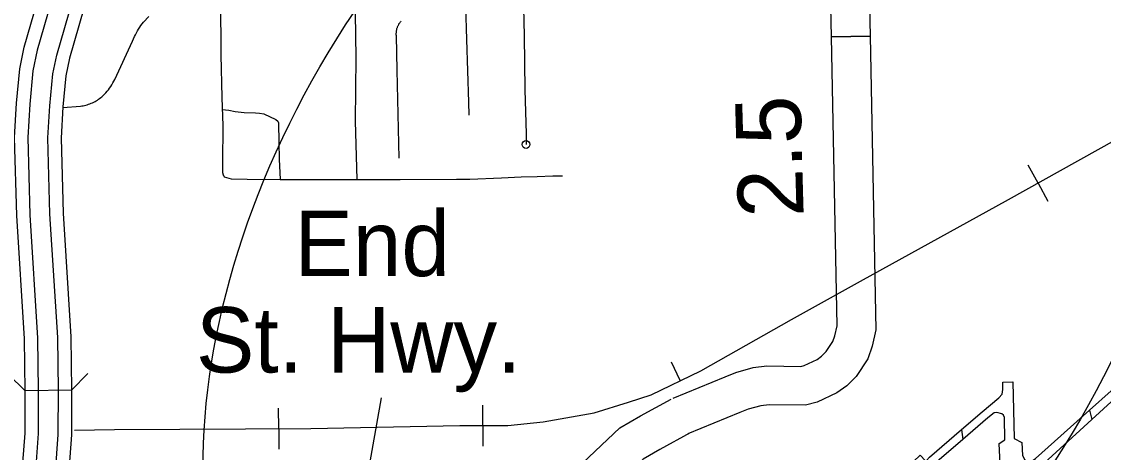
# Model space of a CAD drawing. Extents: x 309348 to 309445, y 336383 to 336484.
# Drawn here: x 309351.067 to 309352.465, y 336399.638 to 336400.194 of the extents above; entities that cross this region are included whole.
import ezdxf

# ---------------------------------------------------------------- set-up
doc = ezdxf.new("R2010")
doc.units = 0
doc.layers.add('R_Annotation', color=7, linetype='Continuous')

msp = doc.modelspace()

# ---------------------------------------------------------------- linework, layer by layer
at = {"layer": 'R_Annotation'}
for p, q in [((309352.1133, 336400.1741), (309352.1634, 336400.1751)), ((309352.3805, 336399.9852), (309352.3676, 336400.0083)), ((309352.3805, 336399.9852), (309352.3933, 336399.9621)), ((309351.918, 336399.7302), (309351.9065, 336399.754)), ((309351.1312, 336399.7179), (309351.0712, 336399.7171)), ((309351.1012, 336399.7175), (309351.1012, 336399.7175)), ((309351.5313, 336399.7081), (309351.4776, 336399.4011)), ((309351.399, 336399.6682), (309351.3988, 336399.6946)), ((309351.663, 336399.672), (309351.663, 336399.6984)), ((309351.399, 336399.6682), (309351.3991, 336399.6418)), ((309351.663, 336399.672), (309351.663, 336399.6456))]:
    msp.add_line(p, q, dxfattribs=at)
msp.add_lwpolyline([(309352.0852, 336401.5472), (309352.1342, 336401.5816), (309352.1376, 336401.4649), (309352.1413, 336401.2113), (309352.1414, 336401.1436), (309352.1437, 336401.068), (309352.1443, 336400.9364), (309352.1473, 336400.8071), (309352.1554, 336400.5429), (309352.1634, 336400.1751), (309352.1133, 336400.1741), (309352.1054, 336400.5416), (309352.0973, 336400.8057), (309352.0943, 336400.9357), (309352.0936, 336401.0671), (309352.0914, 336401.1428), (309352.0913, 336401.2109), (309352.0876, 336401.4638)], close=True, dxfattribs=at)
for points in [[(309351.0727, 336399.4543), (309351.0557, 336399.4536), (309351.0515, 336399.4801), (309351.0657, 336399.5912), (309351.071, 336399.6624), (309351.0712, 336399.7171), (309351.0703, 336399.7842), (309351.0603, 336399.9436), (309351.0576, 336400.0443), (309351.0601, 336400.0883), (309351.0645, 336400.1326), (309351.0701, 336400.1608), (309351.1591, 336400.4684), (309351.1742, 336400.5173), (309351.1893, 336400.5085)], [(309351.1893, 336400.5085), (309351.1754, 336400.4635), (309351.0867, 336400.1568), (309351.0813, 336400.1301), (309351.0771, 336400.087), (309351.0746, 336400.0441), (309351.0773, 336399.9444), (309351.0873, 336399.7849), (309351.0882, 336399.7173), (309351.088, 336399.6617), (309351.0827, 336399.5895), (309351.0684, 336399.4788), (309351.0727, 336399.4543)], [(309351.2142, 336400.5011), (309351.2313, 336400.4986), (309351.2166, 336400.4512), (309351.1285, 336400.1465), (309351.1239, 336400.1237), (309351.1199, 336400.0836), (309351.1177, 336400.0434), (309351.1203, 336399.9463), (309351.1303, 336399.7865), (309351.1312, 336399.7179), (309351.131, 336399.6601), (309351.1255, 336399.5852), (309351.114, 336399.4958), (309351.1114, 336399.4754), (309351.1057, 336399.4547), (309351.0887, 336399.4547)], [(309351.0887, 336399.4547), (309351.0944, 336399.4767), (309351.0971, 336399.4979), (309351.1086, 336399.5869), (309351.114, 336399.6607), (309351.1142, 336399.7177), (309351.1133, 336399.7858), (309351.1033, 336399.9456), (309351.1006, 336400.0437), (309351.103, 336400.085), (309351.1071, 336400.1262), (309351.112, 336400.1506), (309351.2003, 336400.4561), (309351.2142, 336400.5011)], [(309351.6156, 336400.2798), (309351.6185, 336400.2719), (309351.6226, 336400.2646), (309351.6252, 336400.2617), (309351.6287, 336400.2592), (309351.6338, 336400.2585), (309351.657, 336400.2601), (309351.6964, 336400.2624), (309351.7068, 336400.2611), (309351.7126, 336400.2576), (309351.7142, 336400.2544), (309351.7145, 336400.2487), (309351.7164, 336400.1756), (309351.7173, 336400.1057), (309351.7186, 336400.0488), (309351.7186, 336400.0351)], [(309351.6393, 336400.2572), (309351.6419, 336400.1707)], [(309351.4972, 336400.2338), (309351.4985, 336400.147), (309351.4982, 336400.1064)], [(309351.1349, 336399.6663), (309351.1866, 336399.6672), (309351.4404, 336399.6684), (309351.6331, 336399.672), (309351.6949, 336399.672), (309351.7409, 336399.6769), (309351.8069, 336399.6884), (309351.8512, 336399.7023), (309351.8802, 336399.712), (309351.9445, 336399.7429), (309352.062, 336399.809), (309352.151, 336399.8586), (309352.3425, 336399.9641), (309352.5254, 336400.0659), (309352.692, 336400.158), (309352.8047, 336400.2198)], [(309351.1349, 336399.6663), (309351.1866, 336399.6672), (309351.4404, 336399.6684), (309351.6331, 336399.672), (309351.6949, 336399.672), (309351.7409, 336399.6769), (309351.8069, 336399.6884), (309351.8512, 336399.7023), (309351.8802, 336399.712), (309351.9445, 336399.7429), (309352.062, 336399.809), (309352.151, 336399.8586), (309352.3425, 336399.9641), (309352.5254, 336400.0659), (309352.692, 336400.158), (309352.8047, 336400.2198)], [(309351.3237, 336400.2223), (309351.3243, 336400.151), (309351.3254, 336400.0959), (309351.3269, 336400.0591), (309351.3262, 336400.012), (309351.3263, 336399.9995), (309351.3263, 336399.9991), (309351.3264, 336399.9987), (309351.3264, 336399.9983), (309351.3265, 336399.998), (309351.3266, 336399.9976), (309351.3267, 336399.9973), (309351.3268, 336399.9969), (309351.3269, 336399.9965), (309351.327, 336399.9962), (309351.3271, 336399.9958), (309351.3273, 336399.9955), (309351.3274, 336399.9952), (309351.3276, 336399.9948), (309351.3278, 336399.9945), (309351.328, 336399.9942), (309351.3282, 336399.9939), (309351.3284, 336399.9936), (309351.3285, 336399.9935)], [(309351.1199, 336400.083), (309351.1427, 336400.0847), (309351.1445, 336400.0849), (309351.1463, 336400.0852), (309351.1481, 336400.0856), (309351.1498, 336400.086), (309351.1515, 336400.0865), (309351.1532, 336400.0871), (309351.1549, 336400.0877), (309351.1566, 336400.0884), (309351.1583, 336400.0891), (309351.1599, 336400.0899), (309351.1615, 336400.0907), (309351.163, 336400.0916), (309351.1646, 336400.0925), (309351.1661, 336400.0935), (309351.1675, 336400.0945), (309351.169, 336400.0956), (309351.1704, 336400.0968), (309351.1717, 336400.0979), (309351.173, 336400.0992), (309351.1743, 336400.1004), (309351.1755, 336400.1018), (309351.1772, 336400.1038), (309351.1789, 336400.1058), (309351.1804, 336400.1079), (309351.1819, 336400.1101), (309351.1833, 336400.1123), (309351.1846, 336400.1146), (309351.1858, 336400.1169), (309351.187, 336400.1192), (309351.2099, 336400.1686), (309351.2126, 336400.1744), (309351.2137, 336400.1769), (309351.215, 336400.1793), (309351.2163, 336400.1817), (309351.2178, 336400.1841), (309351.2193, 336400.1864), (309351.2208, 336400.1886), (309351.2225, 336400.1908), (309351.2242, 336400.1929), (309351.2309, 336400.2002)], [(309351.557, 336400.1942), (309351.5564, 336400.1936), (309351.5559, 336400.193), (309351.5554, 336400.1923), (309351.5549, 336400.1917), (309351.5544, 336400.191), (309351.554, 336400.1903), (309351.5536, 336400.1896), (309351.5532, 336400.1889), (309351.5528, 336400.1881), (309351.5525, 336400.1874), (309351.5522, 336400.1866), (309351.5519, 336400.1858), (309351.5516, 336400.1851), (309351.5514, 336400.1843), (309351.5512, 336400.1835), (309351.551, 336400.1827), (309351.5508, 336400.1819), (309351.5507, 336400.181), (309351.5506, 336400.1802), (309351.5506, 336400.1794), (309351.5505, 336400.1786), (309351.5505, 336400.1778), (309351.5505, 336400.1769), (309351.5506, 336400.1761), (309351.5506, 336400.1753), (309351.5516, 336400.1312), (309351.5543, 336400.0176)], [(309351.6419, 336400.1707), (309351.6442, 336400.0897)], [(309351.9089, 336399.7077), (309351.976, 336399.7352), (309351.9898, 336399.7408), (309352.0123, 336399.7469), (309352.0301, 336399.7491), (309352.074, 336399.7485), (309352.0782, 336399.7496), (309352.0948, 336399.7574), (309352.1007, 336399.7618), (309352.1067, 336399.7676), (309352.1154, 336399.7805), (309352.118, 336399.7882), (309352.1209, 336399.8009), (309352.1133, 336400.1741)], [(309352.1634, 336400.1751), (309352.171, 336399.7958), (309352.1662, 336399.7745), (309352.1606, 336399.7581), (309352.1453, 336399.7354), (309352.1332, 336399.7236), (309352.1205, 336399.7143), (309352.0951, 336399.7022), (309352.0798, 336399.6984), (309352.0329, 336399.6991), (309352.022, 336399.6977), (309352.0057, 336399.6933), (309351.9948, 336399.6889), (309351.928, 336399.6614)], [(309351.4982, 336400.1064), (309351.4978, 336400.0652), (309351.5001, 336399.9899)], [(309351.6442, 336400.0897), (309351.6447, 336400.0728)], [(309351.326, 336400.0805), (309351.3346, 336400.0794), (309351.3428, 336400.0778), (309351.3541, 336400.0765), (309351.3691, 336400.0758), (309351.374, 336400.0756), (309351.3797, 336400.0745), (309351.3954, 336400.0672), (309351.3978, 336400.0654), (309351.3987, 336400.063), (309351.3992, 336400.0378), (309351.3996, 336400.0162), (309351.4007, 336399.9901)], [(309351.3285, 336399.9935), (309351.3375, 336399.9907), (309351.3583, 336399.9903), (309351.4007, 336399.9901)], [(309351.4007, 336399.9901), (309351.4522, 336399.9901), (309351.5063, 336399.9899), (309351.5558, 336399.9899), (309351.6287, 336399.9905), (309351.6459, 336399.9903), (309351.6868, 336399.9919), (309351.7124, 336399.9934), (309351.733, 336399.9936), (309351.7533, 336399.9945), (309351.7657, 336399.9945)], [(309351.0497, 336399.738), (309351.0712, 336399.7171)], [(309351.1312, 336399.7179), (309351.1522, 336399.7394)], [(309352.3082, 336399.69), (309352.3298, 336399.7081), (309352.3342, 336399.7125), (309352.3351, 336399.7187), (309352.3348, 336399.7283), (309352.3481, 336399.7286), (309352.3497, 336399.6555), (309352.3597, 336399.6503), (309352.3603, 336399.6335), (309352.3634, 336399.6279), (309352.3665, 336399.6263), (309352.373, 336399.6266), (309352.3771, 336399.6294), (309352.4471, 336399.6919)], [(309352.475, 336399.7168), (309352.4471, 336399.6919)], [(309351.728, 336399.5631), (309351.8399, 336399.669), (309351.8668, 336399.6845), (309351.9063, 336399.7064)], [(309352.4502, 336399.6801), (309352.475, 336399.7028)], [(309352.2814, 336399.667), (309352.3082, 336399.69)], [(309352.3156, 336399.6821), (309352.2833, 336399.6542)], [(309352.3215, 336399.5771), (309352.3301, 336399.5859), (309352.3329, 336399.5958), (309352.3301, 336399.649), (309352.3376, 336399.6537), (309352.3373, 336399.6826), (309352.3357, 336399.6857), (309352.3335, 336399.6873), (309352.327, 336399.6888), (309352.3236, 336399.6885), (309352.3156, 336399.6821)], [(309352.4502, 336399.6801), (309352.3628, 336399.6002), (309352.3643, 336399.5616)], [(309352.4471, 336399.6919), (309352.4502, 336399.6801)], [(309352.1757, 336399.5712), (309352.1701, 336399.5787), (309352.2282, 336399.6338), (309352.2348, 336399.6264), (309352.2361, 336399.6269), (309352.2401, 336399.6314), (309352.2814, 336399.667)], [(309352.2814, 336399.667), (309352.2833, 336399.6542)], [(309351.9306, 336399.6627), (309351.8915, 336399.641), (309351.87, 336399.6286), (309351.7623, 336399.5268)], [(309352.2833, 336399.6542), (309352.2467, 336399.6227), (309352.2454, 336399.6208), (309352.2449, 336399.6187), (309352.2459, 336399.616), (309352.2629, 336399.6001), (309352.2549, 336399.5906), (309352.2512, 336399.585), (309352.2499, 336399.5797), (309352.2502, 336399.5744), (309352.2518, 336399.5697), (309352.2536, 336399.5654), (309352.2592, 336399.5596), (309352.2706, 336399.5495), (309352.2748, 336399.5474), (309352.2801, 336399.5466), (309352.2865, 336399.5482), (309352.292, 336399.5506), (309352.3215, 336399.5771)]]:
    msp.add_lwpolyline(points, dxfattribs=at)
msp.add_circle((309351.7186, 336400.0351), 0.005, dxfattribs=at)
msp.add_ellipse((309351.9438, 336399.908), major_axis=(-0.4621, -0.6892), ratio=0.64799, dxfattribs=at)

# ---------------------------------------------------------------- texts
msp.add_text('2.5', height=0.08451, rotation=91.6147, dxfattribs=at).set_placement((309352.0776, 336399.942))
for s, p in [('End', (309351.4193, 336399.8651)), ('St. Hwy.', (309351.292, 336399.7406))]:
    msp.add_text(s, height=0.08451, dxfattribs=at).set_placement(p)

doc.saveas('drawing.dxf')
